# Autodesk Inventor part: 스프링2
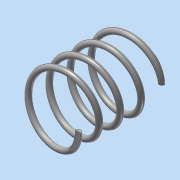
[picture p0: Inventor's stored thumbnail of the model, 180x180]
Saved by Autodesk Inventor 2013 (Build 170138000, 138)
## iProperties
Created: 2014-11
Part Number: 스프링2
Material: 강철, 연강
Document SubType Name: Modeling
Designer: Administrator
Density: 7.86 g/cm^3
Mass: 2.84032 g
Surface Area: 9.76414 cm^2
Volume: 0.361364 cm^3
Author: Administrator
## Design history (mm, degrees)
sketch "스케치1"
  geometry: L1 (0, 0)-(0, 23); L2 (0, 0)-(8.25, 0); L3 (0, 23)-(8.25, 23); C1 r 0.75 at (8.25, 0)
  constraints: 6 end point, 2 parallel, 1 centre point, 1 coincident, 1 perpendicular, 1 vertical
  dimensions: "d0" = 23 distance of L1.start L1.end (derived); "d1" = 8.25 distance of L1.end L3.end; "d2" = 1.5 diameter of C1
feature "코일1" sketch "스케치1" pitch "d3" = 10; turns "d5" = 4; dims "d4" = 23 (= d0), "d6" = 0, angle "d7" = 90 deg, angle "d8" = 90 deg, "d9" = 0, "d10" = 0
sketch "스케치2"
  geometry: L1 (23, 12)-(0, 12); L2 (0, 12)-(0, -12); L3 (0, -12)-(23, -12); L4 (23, -12)-(23, 12); 2 further points
  constraints: 8 end point, 2 coincident, 2 parallel, 1 horizontal, 1 midpoint, 1 perpendicular
  dimensions: "d11" = 23 distance of L2.end L3.end (derived); "d13" = 24 distance between parallel lines of L3 L1
extrude "돌출1" sketch "스케치2" stored distance "d14" = 10; taper "d15" = 0 deg
node "솔리드1"
